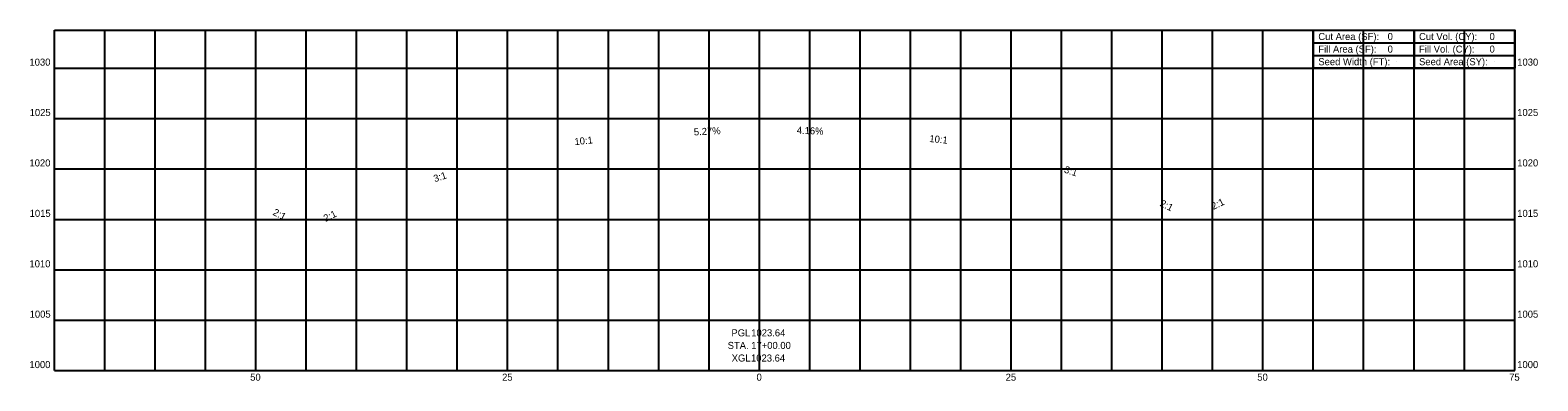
# Model space of a CAD drawing. Extents: x -72 to 77, y 999 to 1034.
import ezdxf

# ---------------------------------------------------------------- set-up
doc = ezdxf.new("R2010")
doc.units = 0
for name, color, linetype in [('Default', 7, 'Continuous'), ('DT_X_Break_Line', 7, 'Continuous'), ('DT_X_Spot_Elev', 7, 'Continuous'), ('DT_X_Void', 7, 'Continuous'), ('SH_Data', 7, 'Continuous')]:
    doc.layers.add(name, color=color, linetype=linetype)

msp = doc.modelspace()

# ---------------------------------------------------------------- linework, layer by layer
at = {"layer": 'Default'}
msp.add_circle((75, 1033.76), 0.000417, dxfattribs=at)
msp.add_circle((75, 1033.76), 0.000417, dxfattribs=at)
msp.add_circle((75, 1033.76), 0.000417, dxfattribs=at)
msp.add_circle((75, 1033.76), 0.000417, dxfattribs=at)
msp.add_circle((75, 1033.76), 0.000417, dxfattribs=at)
msp.add_circle((75, 1033.76), 0.000417, dxfattribs=at)
msp.add_circle((75, 1033.76), 0.000417, dxfattribs=at)
msp.add_circle((75, 1033.76), 0.000417, dxfattribs=at)
msp.add_circle((75, 1033.76), 0.000417, dxfattribs=at)
msp.add_circle((75, 1033.76), 0.000417, dxfattribs=at)
msp.add_circle((75, 1033.76), 0.000417, dxfattribs=at)
msp.add_circle((75, 1033.76), 0.000417, dxfattribs=at)
at = {"layer": 'DT_X_Break_Line'}
for p, q in [((-70, 1033.76), (75, 1033.76)), ((-70, 1000), (-70, 1033.76)), ((-65, 1000), (-65, 1033.76)), ((-60, 1000), (-60, 1033.76)), ((-55, 1000), (-55, 1033.76)), ((-50, 1000), (-50, 1033.76)), ((-45, 1000), (-45, 1033.76)), ((-40, 1000), (-40, 1033.76)), ((-35, 1000), (-35, 1033.76)), ((-30, 1000), (-30, 1033.76)), ((-25, 1000), (-25, 1033.76)), ((-20, 1000), (-20, 1033.76)), ((-15, 1000), (-15, 1033.76)), ((-10, 1000), (-10, 1033.76)), ((-5, 1000), (-5, 1033.76)), ((0, 1000), (0, 1033.76)), ((5, 1000), (5, 1033.76)), ((10, 1000), (10, 1033.76)), ((15, 1000), (15, 1033.76)), ((20, 1000), (20, 1033.76)), ((25, 1000), (25, 1033.76)), ((30, 1000), (30, 1033.76)), ((35, 1000), (35, 1033.76)), ((40, 1000), (40, 1033.76)), ((45, 1000), (45, 1033.76)), ((50, 1000), (50, 1033.76)), ((55, 1000), (55, 1033.76)), ((60, 1000), (60, 1033.76)), ((65, 1000), (65, 1033.76)), ((70, 1000), (70, 1033.76)), ((75, 1000), (75, 1033.76)), ((-70, 1030), (75, 1030)), ((-70, 1025), (75, 1025)), ((-70, 1020), (75, 1020)), ((-70, 1015), (75, 1015)), ((-70, 1010), (75, 1010)), ((-70, 1005), (75, 1005)), ((-70, 1000), (75, 1000))]:
    msp.add_line(p, q, dxfattribs=at)
at = {"layer": 'DT_X_Void'}
msp.add_lwpolyline([(55, 1033.76), (75, 1033.76), (75, 1030.01), (55, 1030.01)], close=True, dxfattribs=at)
at = {"layer": 'SH_Data'}
for p, q in [((55, 1033.76), (75, 1033.76)), ((55, 1033.76), (55, 1031.26)), ((65, 1033.76), (65, 1030.01)), ((75, 1033.76), (75, 1031.26)), ((55, 1032.51), (75, 1032.51)), ((55, 1031.26), (75, 1031.26)), ((63.3, 1030.64), (63.3, 1030.64)), ((72.95, 1030.64), (72.95, 1030.64))]:
    msp.add_line(p, q, dxfattribs=at)
msp.add_lwpolyline([(55, 1031.26), (55, 1030.01), (75, 1030.01), (75, 1031.26)], dxfattribs=at)

# ---------------------------------------------------------------- texts
at = {"layer": 'DT_X_Spot_Elev'}
for s, p in [('Cut Area (SF):', (55.5, 1032.79)), ('0', (62.38, 1032.79)), ('Cut Vol. (CY):', (65.5, 1032.79)), ('0', (72.5, 1032.79)), ('Fill Area (SF):', (55.5, 1031.54)), ('0', (62.38, 1031.54)), ('Fill Vol. (CY):', (65.5, 1031.54)), ('0', (72.5, 1031.54)), ('1030', (-72.48, 1030.25)), ('Seed Width (FT):', (55.5, 1030.29)), ('Seed Area (SY):', (65.5, 1030.29)), ('1030', (75.25, 1030.25)), ('1025', (-72.46, 1025.25)), ('1025', (75.25, 1025.25)), ('1020', (-72.48, 1020.25)), ('1020', (75.25, 1020.25)), ('1015', (-72.46, 1015.25)), ('1015', (75.25, 1015.25)), ('1010', (-72.48, 1010.25)), ('1010', (75.25, 1010.25)), ('1005', (-72.46, 1005.25)), ('1005', (75.25, 1005.25)), ('PGL ', (-2.78, 1003.4)), ('1023.64', (-0.81, 1003.4)), ('STA. 17+00.00', (-3.15, 1002.15)), ('XGL ', (-2.75, 1000.9)), ('1023.64', (-0.83, 1000.9)), ('1000', (-72.48, 1000.25)), ('1000', (75.25, 1000.25)), ('50', (-50.56, 999)), ('25', (-25.55, 999)), ('0', (-0.28, 999)), ('25', (24.45, 999)), ('50', (49.44, 999)), ('75', (74.45, 999))]:
    msp.add_text(s, height=0.7, dxfattribs=at).set_placement(p)
for s, rotation, p in [('5.27%', 3.0187, (-6.49, 1023.32)), ('4.16%', 357.6166, (3.7, 1023.5)), ('10:1', 5.7028, (-18.33, 1022.36)), ('10:1', 354.3116, (16.85, 1022.68)), ('3:1', 18.2561, (-32.23, 1018.68)), ('3:1', 341.7449, (30.2, 1019.66)), ('2:1', 333.4399, (39.7, 1016.36)), ('2:1', 26.2315, (45.08, 1015.93)), ('2:1', 333.442, (-48.38, 1015.48)), ('2:1', 26.5501, (-43.07, 1014.74))]:
    msp.add_text(s, height=0.7, rotation=rotation, dxfattribs=at).set_placement(p)

doc.saveas('drawing.dxf')
